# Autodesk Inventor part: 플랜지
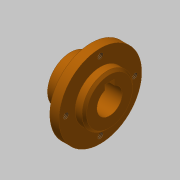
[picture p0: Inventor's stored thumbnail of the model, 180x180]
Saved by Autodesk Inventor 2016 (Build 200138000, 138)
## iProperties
Created: 2019-10
Part Number: 플랜지
Material: 스테인리스강
Document SubType Name: Modeling
Designer: mduedu
Density: 1 g/cm^3
Appearance: 주황색
Author: mduedu
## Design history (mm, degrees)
sketch "스케치1"
  geometry: L1 (0, 0)-(9, 0); L2 (9, 0)-(9, 10); L3 (9, 10)-(0, 10); L4 (0, 10)-(0, 0); L5 (9, 0)-(13, 0); L6 (13, 0)-(13, 18); L7 (13, 18)-(9, 18); L8 (9, 18)-(9, 0); L9 (13, 0)-(17, 0); L10 (17, 0)-(17, 11); L11 (17, 11)-(13, 11); L12 (13, 11)-(13, 0)
  constraints: 24 end point, 6 parallel, 3 horizontal, 3 perpendicular
  dimensions: "d0" = 17 distance between parallel lines of L10 L4; "d2" = 20 diameter of L3 L1; "d3" = 22 diameter of L11 L9; "d4" = 36 diameter of L7 L5; "d5" = 4 distance of L6.end L7.end; "d6" = 4 distance of L10.end L11.end
revolve "회전1" sketch "스케치1" stored, may be unused: angle "d7" = 90 deg
sketch "스케치2"
  geometry: L1 (-2, 5.123)-(2, 5.123); L2 (2, 5.123)-(2, 7.3); L3 (2, 7.3)-(-2, 7.3); L4 (-2, 7.3)-(-2, 5.123); A1 r 5.5 centre (0, 0) between (-2, 5.123) and (2, 5.123); 1 further point
  constraints: 8 end point, 2 parallel, 2 point on circle, 1 centre point, 1 coincident, 1 horizontal, 1 perpendicular
  dimensions: "d8" = 11 diameter of A1; "d10" = 4 distance of L2.end L3.end; "d11" = 7.3 distance from line of L3 point (0, 0)
extrude "돌출1" cut sketch "스케치2" stored distance "d12" = 10; taper "d13" = 0 deg
chamfer "모따기1" distance "d14" = 1; stored, may be unused: second distance "d15" = 2, angle "d16" = 45 deg
chamfer "모따기2" distance "d17" = 1; stored, may be unused: second distance "d18" = 2, angle "d19" = 45 deg
sketch "스케치3" dims "d20" = 30
  geometry: 3 further points
  constraints: 2 vertical alignment, 1 coincident, 2 other
hole "구멍1" sketch "스케치3" at (0, 15) diameter "d21" = 2.459; stored, may be unused: countersink angle "d25" = 90 deg, drill point angle "d27" = 118 deg; dims "d22" = 6, "d23" = 4, "d24" = 2, "d26" = 8
node "솔리드1"
pattern_circular "원형 패턴1" dims angle "d29" = 360 deg
